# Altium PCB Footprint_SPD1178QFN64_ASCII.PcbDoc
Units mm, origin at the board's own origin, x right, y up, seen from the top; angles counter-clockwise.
Board outline 152.4 x 101.6 mm, 2 copper layers (Top Layer, Bottom Layer); 1 components, 0 nets, 66 pads, 16 vias.
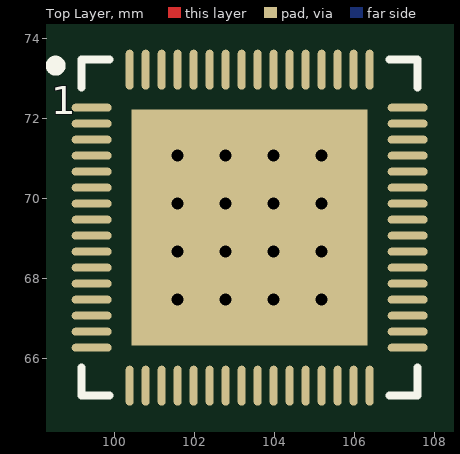
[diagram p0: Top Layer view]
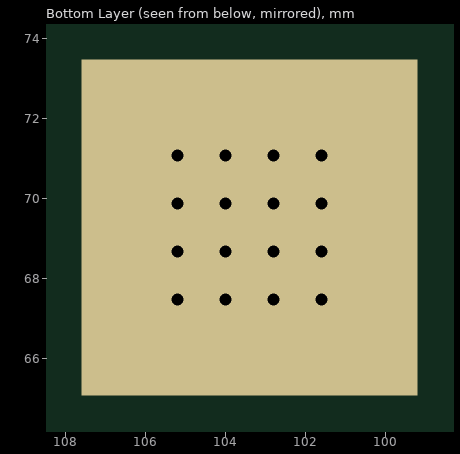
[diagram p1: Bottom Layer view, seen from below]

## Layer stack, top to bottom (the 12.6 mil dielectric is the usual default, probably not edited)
Top Solder: solder mask 0.0102, Solder Resist, Dk 3.5
Top Layer: signal copper 0.0356
Dielectric 1: dielectric 0.32, FR-4, Dk 4.8
Bottom Layer: signal copper 0.0356
Bottom Solder: solder mask 0.0102, Solder Resist, Dk 3.5

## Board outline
25.4,25.4 177.8,25.4 177.8,127 25.4,127

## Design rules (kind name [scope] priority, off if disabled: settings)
AssemblyTestPointUsage [All] p0: scope1count=1 scope1_0_kind=Board scope1_0_value=Board scope2count=1 scope2_0_kind=Board scope2_0_value=Board commentlength=0
AssemblyTestpoint [All] p0: scope1count=1 scope1_0_kind=Board scope1_0_value=Board scope2count=1 scope2_0_kind=Board scope2_0_value=Board commentlength=0
Clearance [All] p0: scope1count=1 scope1_0_kind=Board scope1_0_value=Board scope2count=1 scope2_0_kind=Board scope2_0_value=Board commentlength=0 gap=0.254
Clearance [All] p1: gap=0.254 ignorepadtopadclearanceinfootprint=FALSE except(0: Arc-Hole Track-Hole SMDPad-Hole THPad-Hole Via-Hole Fill-Hole Poly-Hole Region-Hole Text-Hole)
ComponentClearance [All] p0: scope1count=1 scope1_0_kind=Board scope1_0_value=Board scope2count=1 scope2_0_kind=Board scope2_0_value=Board commentlength=0 gap=0.254 collisioncheckmode=3
DiffPairsRouting [All] p0: scope1count=1 scope1_0_kind=Board scope1_0_value=Board scope2count=1 scope2_0_kind=Board scope2_0_value=Board commentlength=0
FabricationTestPointUsage [All] p0: scope1count=1 scope1_0_kind=Board scope1_0_value=Board scope2count=1 scope2_0_kind=Board scope2_0_value=Board commentlength=0 valid=0 allowmultiple=FALSE
FabricationTestpoint [All] p0: scope1count=1 scope1_0_kind=Board scope1_0_value=Board scope2count=1 scope2_0_kind=Board scope2_0_value=Board commentlength=0 side=3 testpointundercomponent=TRUE minsize=1.016 maxsize=2.54 preferedsize=1.524 minholesize=0 maxholesize=1.016 preferedholesize=0.813 testpointgrid=0.025
FanoutControl Fanout_BGA [All] p0 off: scope1count=1 scope1_0_kind=Board scope1_0_value=Board scope2count=1 scope2_0_kind=Board scope2_0_value=Board commentlength=69 // Protel DXP Scope 1 Expression Was: IsBGA   Fanout_BGA (Default Rule)
FanoutControl Fanout_LCC [All] p0 off: scope1count=1 scope1_0_kind=Board scope1_0_value=Board scope2count=1 scope2_0_kind=Board scope2_0_value=Board commentlength=69 // Protel DXP Scope 1 Expression Was: IsLCC   Fanout_LCC (Default Rule)
FanoutControl Fanout_SOIC [All] p0 off: scope1count=1 scope1_0_kind=Board scope1_0_value=Board scope2count=1 scope2_0_kind=Board scope2_0_value=Board commentlength=71 // Protel DXP Scope 1 Expression Was: IsSOIC   Fanout_SOIC (Default Rule)
FanoutControl Fanout_Small [All] p0 off: scope1count=1 scope1_0_kind=Board scope1_0_value=Board scope2count=1 scope2_0_kind=Board scope2_0_value=Board commentlength=84 // Protel DXP Scope 1 Expression Was: (CompPinCount < 5)   Fanout_Small (Default Rule)
FanoutControl Fanout_Default [All] p0: scope1count=1 scope1_0_kind=Board scope1_0_value=Board scope2count=1 scope2_0_kind=Board scope2_0_value=Board commentlength=30 // Fanout_Default (Default Rule)
Height [All] p0: scope1count=1 scope1_0_kind=Board scope1_0_value=Board scope2count=1 scope2_0_kind=Board scope2_0_value=Board commentlength=0
HoleSize [All] p0: scope1count=1 scope1_0_kind=Board scope1_0_value=Board scope2count=1 scope2_0_kind=Board scope2_0_value=Board commentlength=0 absolutevalues=TRUE maxlimit=2.54 minlimit=0.025 maxpercent=80.000 minpercent=20.000
HoleToHoleClearance [All] p0: scope1count=1 scope1_0_kind=Board scope1_0_value=Board scope2count=1 scope2_0_kind=Board scope2_0_value=Board commentlength=0
LayerPairs [All] p0: scope1count=1 scope1_0_kind=Board scope1_0_value=Board scope2count=1 scope2_0_kind=Board scope2_0_value=Board commentlength=0 enforce=TRUE
MinimumSolderMaskSliver [All] p0: scope1count=1 scope1_0_kind=Board scope1_0_value=Board scope2count=1 scope2_0_kind=Board scope2_0_value=Board commentlength=0
NetAntennae [All] p0: scope1count=1 scope1_0_kind=Board scope1_0_value=Board scope2count=1 scope2_0_kind=Board scope2_0_value=Board commentlength=0
PasteMaskExpansion [All] p0: scope1count=1 scope1_0_kind=Board scope1_0_value=Board scope2count=1 scope2_0_kind=Board scope2_0_value=Board commentlength=0 expansion=0
PlaneClearance [All] p0: scope1count=1 scope1_0_kind=Board scope1_0_value=Board scope2count=1 scope2_0_kind=Board scope2_0_value=Board commentlength=0 clearance=0.508
PlaneConnect [All] p0: scope1count=1 scope1_0_kind=Board scope1_0_value=Board scope2count=1 scope2_0_kind=Board scope2_0_value=Board commentlength=0 planeconnectstyle=Relief reliefexpansion=0.508 reliefentries=4 reliefconductorwidth=0.254 reliefairgap=0.254
PolygonConnect [All] p0: scope1count=1 scope1_0_kind=Board scope1_0_value=Board scope2count=1 scope2_0_kind=Board scope2_0_value=Board commentlength=0 connectstyle=Relief reliefconductorwidth=0.254 reliefentries=4 polygonreliefangle="90 Angle"
PolygonConnect [All] p1: connectstyle=Relief reliefconductorwidth=0.254 reliefentries=4 polygonreliefangle="90 Angle" airgapwidth=0.254
RoutingCorners [All] p0: scope1count=1 scope1_0_kind=Board scope1_0_value=Board scope2count=1 scope2_0_kind=Board scope2_0_value=Board commentlength=0 cornerstyle=45-Degree minsetback=2.54 maxsetback=2.54
RoutingLayers [All] p0: scope1count=1 scope1_0_kind=Board scope1_0_value=Board scope2count=1 scope2_0_kind=Board scope2_0_value=Board commentlength=0 top layer=Automatic bottom layer=Automatic
RoutingPriority [All] p0: scope1count=1 scope1_0_kind=Board scope1_0_value=Board scope2count=1 scope2_0_kind=Board scope2_0_value=Board commentlength=0
RoutingTopology [All] p0: scope1count=1 scope1_0_kind=Board scope1_0_value=Board scope2count=1 scope2_0_kind=Board scope2_0_value=Board commentlength=0 topology=Shortest
RoutingVias [All] p0: scope1count=1 scope1_0_kind=Board scope1_0_value=Board scope2count=1 scope2_0_kind=Board scope2_0_value=Board commentlength=0 holewidth=0.711 width=1.27 viastyle="Through Hole" minholewidth=0.711 minwidth=1.27 maxholewidth=0.711 maxwidth=1.27
RoutingVias [All] p1: holewidth=0.711 width=1.27 viastyle="Through Hole" minholewidth=0.711 minwidth=1.27 maxholewidth=0.711 maxwidth=1.27
ShortCircuit [All] p0: scope1count=1 scope1_0_kind=Board scope1_0_value=Board scope2count=1 scope2_0_kind=Board scope2_0_value=Board commentlength=0 allowed=FALSE
SilkToBoardRegionClearance [All] p0: scope1count=1 scope1_0_kind=Board scope1_0_value=Board scope2count=1 scope2_0_kind=Board scope2_0_value=Board commentlength=0
SilkToSilkClearance [All] p0: scope1count=1 scope1_0_kind=Board scope1_0_value=Board scope2count=1 scope2_0_kind=Board scope2_0_value=Board commentlength=0
SilkToSolderMaskClearance [All] p0 off: scope1count=1 scope1_0_kind=Board scope1_0_value=Board scope2count=1 scope2_0_kind=Board scope2_0_value=Board commentlength=44 // Protel DXP Scope 1 Expression Was: IsPad
SolderMaskExpansion [All] p0: scope1count=1 scope1_0_kind=Board scope1_0_value=Board scope2count=1 scope2_0_kind=Board scope2_0_value=Board commentlength=0 expansion=0.102
SolderMaskExpansion [All] p1: expansion=0.102 istentingtop=FALSE
UnRoutedNet [All] p0: scope1count=1 scope1_0_kind=Board scope1_0_value=Board scope2count=1 scope2_0_kind=Board scope2_0_value=Board commentlength=0
UnpouredPolygon [All] p0: scope1count=1 scope1_0_kind=Board scope1_0_value=Board scope2count=1 scope2_0_kind=Board scope2_0_value=Board commentlength=0
Width [All] p0: scope1count=1 scope1_0_kind=Board scope1_0_value=Board scope2count=1 scope2_0_kind=Board scope2_0_value=Board commentlength=0 maxlimit=0.254 minlimit=0.254 preferedwidth=0.254
Width [All] p1: maxlimit=0.254 minlimit=0.254 preferedwidth=0.254
30 further rules are at their usual default settings.

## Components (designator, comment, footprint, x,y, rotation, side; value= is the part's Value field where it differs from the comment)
? "" QFN-64-0.4 99.441,72.263 r0 top

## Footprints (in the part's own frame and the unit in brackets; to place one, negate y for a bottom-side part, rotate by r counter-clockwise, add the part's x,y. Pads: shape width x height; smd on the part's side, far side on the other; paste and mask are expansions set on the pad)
QFN-64-0.4 [mm] "P-0.4,8*8mm"
  rect 5.9x5.9 smd: 0(3.95,-3)
  rect 8.4x8.4 smd far side: 0(3.95,-3)
  oval 1x0.2 smd: 1(0,0) 2(0,-0.4) 3(0,-0.8) 4(0,-1.2) 5(0,-1.6) 6(0,-2) 7(0,-2.4) 8(0,-2.8) 9(0,-3.2) 10(0,-3.6) 11(0,-4) 12(0,-4.4) 13(0,-4.8) 14(0,-5.2) 15(0,-5.6) 16(0,-6) 33(7.9,-6) 34(7.9,-5.6) 35(7.9,-5.2) 36(7.9,-4.8) 37(7.9,-4.4) 38(7.9,-4) 39(7.9,-3.6) 40(7.9,-3.2) 41(7.9,-2.8) 42(7.9,-2.4) 43(7.9,-2) 44(7.9,-1.6) 45(7.9,-1.2) 46(7.9,-0.8) 47(7.9,-0.4) 48(7.9,0)
  oval 0.2x1 smd: 17(0.95,-6.95) 18(1.35,-6.95) 19(1.75,-6.95) 20(2.15,-6.95) 21(2.55,-6.95) 22(2.95,-6.95) 23(3.35,-6.95) 24(3.75,-6.95) 25(4.15,-6.95) 26(4.55,-6.95) 27(4.95,-6.95) 28(5.35,-6.95) 29(5.75,-6.95) 30(6.15,-6.95) 31(6.55,-6.95) 32(6.95,-6.95) 49(6.95,0.95) 50(6.55,0.95) 51(6.15,0.95) 52(5.75,0.95) 53(5.35,0.95) 54(4.95,0.95) 55(4.55,0.95) 56(4.15,0.95) 57(3.75,0.95) 58(3.35,0.95) 59(2.95,0.95) 60(2.55,0.95) 61(2.15,0.95) 62(1.75,0.95) 63(1.35,0.95) 64(0.95,0.95)
  silkscreen extent -1.02,-7.2 8.15,1.2

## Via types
v1: diameter 0.6, hole 0.3, Top Layer to Bottom Layer, 16 vias

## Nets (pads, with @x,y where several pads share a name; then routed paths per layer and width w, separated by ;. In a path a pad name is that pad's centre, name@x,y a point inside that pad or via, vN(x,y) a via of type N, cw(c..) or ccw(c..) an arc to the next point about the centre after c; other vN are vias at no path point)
pads on no net: ?.0 ?.1 ?.2 ?.3 ?.4 ?.5 ?.6 ?.7 ?.8 ?.9 ?.10 ?.11 ?.12 ?.13 ?.14 ?.15 ?.16 ?.17 ?.18 ?.19 ?.20 ?.21 ?.22 ?.23 ?.24 ?.25 ?.26 ?.27 ?.28 ?.29 ?.30 ?.31 ?.32 ?.33 ?.34 ?.35 ?.36 ?.37 ?.38 ?.39 ?.40 ?.41 ?.42 ?.43 ?.44 ?.45 ?.46 ?.47 ?.48 ?.49 ?.50 ?.51 ?.52 ?.53 ?.54 ?.55 ?.56 ?.57 ?.58 ?.59 ?.60 ?.61 ?.62 ?.63 ?.64
copper on no net:
  other v1: 101.591,67.463 102.791,67.463 103.991,67.463 105.191,67.463 101.591,68.663 102.791,68.663 103.991,68.663 105.191,68.663 101.591,69.863 102.791,69.863 103.991,69.863 105.191,69.863 101.591,71.063 102.791,71.063 103.991,71.063 105.191,71.063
